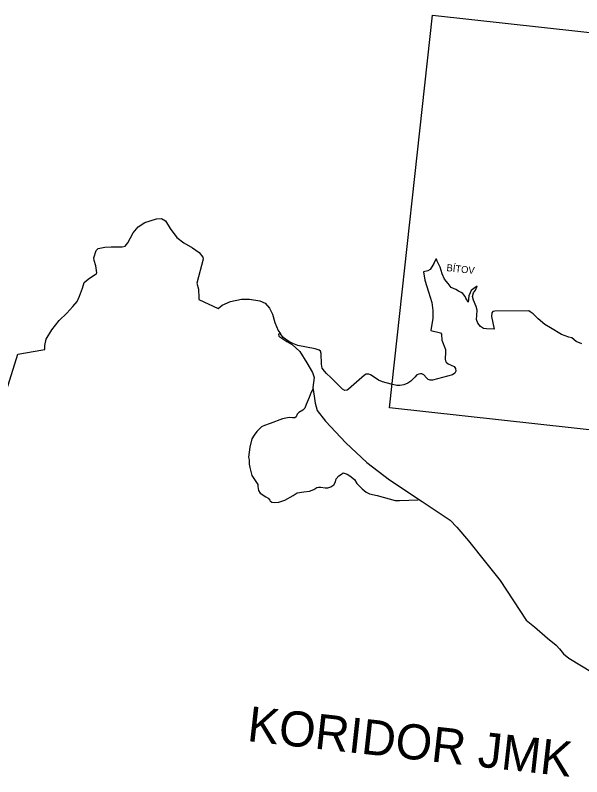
# Model space of a CAD drawing. Extents: x -678204 to -526855, y -1228851 to -1110393.
# Drawn here: x -668785 to -663938, y -1185752 to -1179242 of the extents above; entities that cross this region are included whole.
import ezdxf

# ---------------------------------------------------------------- set-up
doc = ezdxf.new("R2010")
doc.units = 0
for name, color, linetype in [('00_n_cyklo popisy', 7, 'Continuous'), ('00_n_cyklo popisy detaily', 7, 'Continuous'), ('00_n_cyklo prujezdne rekreacni hlavni', 7, 'Continuous'), ('00_n_cyklo prujezdne rekreacni vedlejsi', 7, 'Continuous'), ('00_n_cyklo studie rekreacni vedlejsi', 7, 'Continuous'), ('00_n_cyklo trasovani rekreacni hlavni', 7, 'Continuous'), ('00_n_cyklo trasovani rekreacni vedlejsi', 7, 'Continuous'), ('_HELP', 7, 'Continuous'), ('n_osa_okruh 0 ZAKLADNI', 7, 'Continuous')]:
    doc.layers.add(name, color=color, linetype=linetype)

msp = doc.modelspace()

# ---------------------------------------------------------------- linework, layer by layer
at = {"layer": '00_n_cyklo prujezdne rekreacni hlavni'}
msp.add_lwpolyline([(-668873.8, -1182495.3), (-668764.3, -1182138.1), (-668550.3, -1182100.6), (-668532.5, -1182098.6), (-668532.5, -1182066.1), (-668521.7, -1182011.8), (-668471.4, -1181931.9), (-668409.2, -1181851), (-668343.2, -1181787.9), (-668291.9, -1181732.6), (-668255.4, -1181688.2), (-668235.7, -1181641.9), (-668210, -1181573.8), (-668196.2, -1181527.4), (-668160.7, -1181497.8), (-668089.7, -1181449.5), (-668085.8, -1181444.5), (-668096.6, -1181384.3), (-668110.4, -1181337), (-668111.4, -1181314.3), (-668092.7, -1181253.1), (-668076.9, -1181235.4), (-668019.7, -1181223.5), (-667963.5, -1181221.6), (-667914.1, -1181221.6), (-667870.7, -1181221.6), (-667844.1, -1181215.6), (-667821.4, -1181188), (-667777.1, -1181102.2), (-667734.6, -1181050.9), (-667676.5, -1181012.4), (-667577.8, -1180981.8), (-667534.4, -1180979.8), (-667500.9, -1180998.6), (-667459.5, -1181064.7), (-667403.3, -1181141.6), (-667343.1, -1181188), (-667269.1, -1181230.4), (-667211.9, -1181269.9), (-667181.4, -1181309.4), (-667176.4, -1181327.1), (-667230.2, -1181533.3), (-667218.1, -1181583.4), (-667214.6, -1181657.6), (-667212.9, -1181671.4), (-667049, -1181749.1), (-667015.7, -1181718.8), (-666943.7, -1181688.2), (-666848, -1181668.5), (-666779.9, -1181667.5), (-666693.2, -1181682.3), (-666647.8, -1181703), (-666610.3, -1181746.4), (-666583.7, -1181796.7), (-666563, -1181867.8), (-666535.4, -1181937.8), (-666516.6, -1181966.4), (-666531.4, -1181969.4), (-666530.4, -1181986.2), (-666462.4, -1182029.6), (-666417, -1182056.2), (-666349.9, -1182115.4), (-666289.8, -1182214.1), (-666241.5, -1182296.9), (-666227.6, -1182338.4), (-666239.5, -1182423.2), (-666227.6, -1182498.2), (-666219.7, -1182558), (-666200.7, -1182621.9), (-666131.7, -1182711.7), (-665955.6, -1182896.4), (-665777.8, -1183063.9), (-665582.8, -1183214.1), (-665304.9, -1183397.1), (-665063.3, -1183557.4), (-665006.1, -1183616.6), (-664908.5, -1183735), (-664751.6, -1183930.4), (-664637.2, -1184072.4), (-664413.4, -1184412.8), (-664343.3, -1184470), (-664229.9, -1184567.4), (-664156.7, -1184627.2), (-664127.3, -1184659.3), (-664095.2, -1184699.9), (-664050.1, -1184736.6), (-663846.7, -1184860)], dxfattribs=at)
at = {"layer": '00_n_cyklo prujezdne rekreacni vedlejsi'}
for points in [[(-665204.3, -1181363.3), (-665212.4, -1181379.4), (-665235.4, -1181416.1), (-665253.7, -1181426), (-665291.5, -1181434.6), (-665279.4, -1181506.5), (-665249.7, -1181607.5), (-665221.4, -1181697.5), (-665212, -1181765.9), (-665213.1, -1181831.2), (-665229.1, -1181935.8), (-665146.9, -1181957.9), (-665138.4, -1181967.8), (-665134.3, -1182020.6), (-665103.4, -1182098.3), (-665102.5, -1182121.6), (-665106.5, -1182182.9), (-665103, -1182196.3), (-665096.8, -1182208.3), (-665082.2, -1182220.3), (-665029.6, -1182244), (-665018.3, -1182261.9), (-665016.1, -1182283.3), (-665025.3, -1182301.5), (-665044.4, -1182314.9), (-665215.6, -1182362.3), (-665234.1, -1182361.8), (-665251.3, -1182355.3), (-665266.6, -1182340.4), (-665288, -1182314.4), (-665305.2, -1182308), (-665316.8, -1182306.1), (-665330.9, -1182309.3), (-665348.1, -1182316.1), (-665365.4, -1182334.7), (-665401.5, -1182371.2), (-665425.9, -1182387.7), (-665461.3, -1182401.9), (-665493.5, -1182407.3), (-665519.9, -1182406.7), (-665569.7, -1182396), (-665643.6, -1182376.8), (-665677.4, -1182361.4), (-665722.6, -1182331.2), (-665746.4, -1182316.2), (-665760, -1182309.6), (-665769.6, -1182308.8), (-665781.3, -1182310.3), (-665796.2, -1182319.2), (-665935.2, -1182438.8), (-665945.3, -1182445.8), (-665966.2, -1182448.2), (-665985.7, -1182438.6), (-666056.4, -1182368.1), (-666085.8, -1182338.5), (-666122.9, -1182305), (-666140.3, -1182283.8), (-666159.2, -1182259.5), (-666165.9, -1182224.7), (-666168.4, -1182133.9), (-666172.4, -1182112.2), (-666184, -1182105.1), (-666220, -1182094.2), (-666367.1, -1182064), (-666408.9, -1182049.2), (-666443.6, -1182031.2), (-666493.1, -1181996.5), (-666516.6, -1181966.4)], [(-663937, -1182049.9), (-663985.4, -1182031.9), (-664023.6, -1181999.3), (-664049.5, -1181992.6), (-664112.5, -1181970.1), (-664205.8, -1181912.7), (-664255.3, -1181885.7), (-664309.8, -1181836.8), (-664352.5, -1181794), (-664379.5, -1181777.2), (-664389.7, -1181769.3), (-664683.2, -1181771.5), (-664698.9, -1181773.8), (-664706.8, -1181786.2), (-664710.1, -1181817.7), (-664688.8, -1181924.5), (-664752.9, -1181922.3), (-664777.6, -1181920), (-664804.6, -1181903.1), (-664827.1, -1181875), (-664839.5, -1181842.4), (-664837.2, -1181807.5), (-664832.7, -1181762.6), (-664840.6, -1181731.1), (-664865.3, -1181678.2), (-664874.3, -1181646.7), (-664865.3, -1181615.2), (-664846.2, -1181590.5), (-664833.8, -1181557.8), (-664861.1, -1181576.7), (-664884.5, -1181596), (-664893.9, -1181615.7), (-664904.7, -1181639.7), (-664910.3, -1181695.2)], [(-666236, -1182436.1), (-666254, -1182462.6), (-666271.7, -1182510), (-666297.2, -1182570.4), (-666308.2, -1182600.6), (-666324.2, -1182617.3), (-666359.6, -1182638.5), (-666372.4, -1182652), (-666381.4, -1182673.8), (-666394.3, -1182684.1), (-666413.5, -1182683.5), (-666438.6, -1182680.9), (-666455.9, -1182684.1), (-666497.1, -1182693.1), (-666603.7, -1182732.3), (-666651.9, -1182749), (-666677, -1182760.6), (-666717.5, -1182800.5), (-666741.3, -1182830.7), (-666759.9, -1182864.1), (-666779.2, -1182933.5), (-666790.7, -1183019), (-666782.7, -1183041.3), (-666783.3, -1183078.3), (-666778.8, -1183108.4), (-666760.9, -1183176.4), (-666709.5, -1183253.7), (-666708.9, -1183270.5), (-666702.4, -1183305.8), (-666688.3, -1183326.4), (-666640.8, -1183357.2), (-666620.2, -1183368.8), (-666607.3, -1183386.8), (-666603.5, -1183393.2), (-666590.6, -1183403.5), (-666566.2, -1183408), (-666528.9, -1183404.1), (-666479.5, -1183386.1), (-666406.9, -1183346.3), (-666372.2, -1183325.7), (-666316.3, -1183315.4), (-666267.4, -1183309), (-666231.4, -1183296.8), (-666205.1, -1183279.5), (-666190.9, -1183276.2), (-666170.4, -1183276.9), (-666134.4, -1183282.7), (-666110, -1183280.7), (-666084.9, -1183273.7), (-666058.6, -1183255), (-666045.1, -1183229.3), (-666038.7, -1183204.9), (-666017.5, -1183179.2), (-665993.7, -1183163.8), (-665978.9, -1183154.1), (-665945.3, -1183164.7), (-665922.2, -1183179.5), (-665882.3, -1183211.6), (-665862.4, -1183245.1), (-665818.1, -1183288.8), (-665781.5, -1183317.7), (-665754.2, -1183332.8), (-665688, -1183348.2), (-665534.9, -1183389.4), (-665496.3, -1183389.4), (-665338.2, -1183384.9)]]:
    msp.add_lwpolyline(points, dxfattribs=at)
at = {"layer": '00_n_cyklo studie rekreacni vedlejsi'}
for points in [[(-664910.3, -1181695.2), (-664920.9, -1181675.9), (-664928.6, -1181660.2), (-664936, -1181645.9), (-664947, -1181631), (-664955.1, -1181621.5), (-664971.2, -1181610.8), (-664992.6, -1181599.4), (-665016.4, -1181585.2), (-665055.7, -1181569.1), (-665081.9, -1181536.3), (-665112.2, -1181496.8), (-665131.3, -1181453), (-665150.3, -1181396.2), (-665175.5, -1181345.3), (-665181.6, -1181327), (-665186.1, -1181327.3), (-665204.3, -1181363.3)], [(-664910.3, -1181695.2), (-664910.3, -1181695.2)]]:
    msp.add_lwpolyline(points, dxfattribs=at)
at = {"layer": '00_n_cyklo trasovani rekreacni hlavni'}
msp.add_lwpolyline([(-668873.8, -1182495.3), (-668764.3, -1182138.1), (-668550.3, -1182100.6), (-668532.5, -1182098.6), (-668532.5, -1182066.1), (-668521.7, -1182011.8), (-668471.4, -1181931.9), (-668409.2, -1181851), (-668343.2, -1181787.9), (-668291.9, -1181732.6), (-668255.4, -1181688.2), (-668235.7, -1181641.9), (-668210, -1181573.8), (-668196.2, -1181527.4), (-668160.7, -1181497.8), (-668089.7, -1181449.5), (-668085.8, -1181444.5), (-668096.6, -1181384.3), (-668110.4, -1181337), (-668111.4, -1181314.3), (-668092.7, -1181253.1), (-668076.9, -1181235.4), (-668019.7, -1181223.5), (-667963.5, -1181221.6), (-667914.1, -1181221.6), (-667870.7, -1181221.6), (-667844.1, -1181215.6), (-667821.4, -1181188), (-667777.1, -1181102.2), (-667734.6, -1181050.9), (-667676.5, -1181012.4), (-667577.8, -1180981.8), (-667534.4, -1180979.8), (-667500.9, -1180998.6), (-667459.5, -1181064.7), (-667403.3, -1181141.6), (-667343.1, -1181188), (-667269.1, -1181230.4), (-667211.9, -1181269.9), (-667181.4, -1181309.4), (-667176.4, -1181327.1), (-667230.2, -1181533.3), (-667218.1, -1181583.4), (-667214.6, -1181657.6), (-667212.9, -1181671.4), (-667049, -1181749.1), (-667015.7, -1181718.8), (-666943.7, -1181688.2), (-666848, -1181668.5), (-666779.9, -1181667.5), (-666693.2, -1181682.3), (-666647.8, -1181703), (-666610.3, -1181746.4), (-666583.7, -1181796.7), (-666563, -1181867.8), (-666535.4, -1181937.8), (-666516.6, -1181966.4), (-666531.4, -1181969.4), (-666530.4, -1181986.2), (-666462.4, -1182029.6), (-666417, -1182056.2), (-666349.9, -1182115.4), (-666289.8, -1182214.1), (-666241.5, -1182296.9), (-666227.6, -1182338.4), (-666239.5, -1182423.2), (-666227.6, -1182498.2), (-666219.7, -1182558), (-666200.7, -1182621.9), (-666131.7, -1182711.7), (-665955.6, -1182896.4), (-665777.8, -1183063.9), (-665582.8, -1183214.1), (-665304.9, -1183397.1), (-665063.3, -1183557.4), (-665006.1, -1183616.6), (-664908.5, -1183735), (-664751.6, -1183930.4), (-664637.2, -1184072.4), (-664413.4, -1184412.8), (-664343.3, -1184470), (-664229.9, -1184567.4), (-664156.7, -1184627.2), (-664127.3, -1184659.3), (-664095.2, -1184699.9), (-664050.1, -1184736.6), (-663846.7, -1184860)], dxfattribs=at)
at = {"layer": '00_n_cyklo trasovani rekreacni vedlejsi'}
for points in [[(-664910.3, -1181695.2), (-664920.9, -1181675.9), (-664928.6, -1181660.2), (-664936, -1181645.9), (-664947, -1181631), (-664955.1, -1181621.5), (-664971.2, -1181610.8), (-664992.6, -1181599.4), (-665016.4, -1181585.2), (-665055.7, -1181569.1), (-665081.9, -1181536.3), (-665112.2, -1181496.8), (-665131.3, -1181453), (-665150.3, -1181396.2), (-665175.5, -1181345.3), (-665181.6, -1181327), (-665186.1, -1181327.3), (-665212.4, -1181379.4), (-665235.4, -1181416.1), (-665253.7, -1181426), (-665291.5, -1181434.6), (-665279.4, -1181506.5), (-665249.7, -1181607.5), (-665221.4, -1181697.5), (-665212, -1181765.9), (-665213.1, -1181831.2), (-665229.1, -1181935.8), (-665146.9, -1181957.9), (-665138.4, -1181967.8), (-665134.3, -1182020.6), (-665103.4, -1182098.3), (-665102.5, -1182121.6), (-665106.5, -1182182.9), (-665103, -1182196.3), (-665096.8, -1182208.3), (-665082.2, -1182220.3), (-665029.6, -1182244), (-665018.3, -1182261.9), (-665016.1, -1182283.3), (-665025.3, -1182301.5), (-665044.4, -1182314.9), (-665215.6, -1182362.3), (-665234.1, -1182361.8), (-665251.3, -1182355.3), (-665266.6, -1182340.4), (-665288, -1182314.4), (-665305.2, -1182308), (-665316.8, -1182306.1), (-665330.9, -1182309.3), (-665348.1, -1182316.1), (-665365.4, -1182334.7), (-665401.5, -1182371.2), (-665425.9, -1182387.7), (-665461.3, -1182401.9), (-665493.5, -1182407.3), (-665519.9, -1182406.7), (-665569.7, -1182396), (-665643.6, -1182376.8), (-665677.4, -1182361.4), (-665722.6, -1182331.2), (-665746.4, -1182316.2), (-665760, -1182309.6), (-665769.6, -1182308.8), (-665781.3, -1182310.3), (-665796.2, -1182319.2), (-665935.2, -1182438.8), (-665945.3, -1182445.8), (-665966.2, -1182448.2), (-665985.7, -1182438.6), (-666056.4, -1182368.1), (-666085.8, -1182338.5), (-666122.9, -1182305), (-666140.3, -1182283.8), (-666159.2, -1182259.5), (-666165.9, -1182224.7), (-666168.4, -1182133.9), (-666172.4, -1182112.2), (-666184, -1182105.1), (-666220, -1182094.2), (-666367.1, -1182064), (-666408.9, -1182049.2), (-666443.6, -1182031.2), (-666493.1, -1181996.5), (-666516.6, -1181966.4)], [(-663937, -1182049.9), (-663985.4, -1182031.9), (-664023.6, -1181999.3), (-664049.5, -1181992.6), (-664112.5, -1181970.1), (-664205.8, -1181912.7), (-664255.3, -1181885.7), (-664309.8, -1181836.8), (-664352.5, -1181794), (-664379.5, -1181777.2), (-664389.7, -1181769.3), (-664683.2, -1181771.5), (-664698.9, -1181773.8), (-664706.8, -1181786.2), (-664710.1, -1181817.7), (-664688.8, -1181924.5), (-664752.9, -1181922.3), (-664777.6, -1181920), (-664804.6, -1181903.1), (-664827.1, -1181875), (-664839.5, -1181842.4), (-664837.2, -1181807.5), (-664832.7, -1181762.6), (-664840.6, -1181731.1), (-664865.3, -1181678.2), (-664874.3, -1181646.7), (-664865.3, -1181615.2), (-664846.2, -1181590.5), (-664833.8, -1181557.8), (-664861.1, -1181576.7), (-664884.5, -1181596), (-664893.9, -1181615.7), (-664904.7, -1181639.7), (-664910.3, -1181695.2)], [(-666236, -1182436.1), (-666254, -1182462.6), (-666271.7, -1182510), (-666297.2, -1182570.4), (-666308.2, -1182600.6), (-666324.2, -1182617.3), (-666359.6, -1182638.5), (-666372.4, -1182652), (-666381.4, -1182673.8), (-666394.3, -1182684.1), (-666413.5, -1182683.5), (-666438.6, -1182680.9), (-666455.9, -1182684.1), (-666497.1, -1182693.1), (-666603.7, -1182732.3), (-666651.9, -1182749), (-666677, -1182760.6), (-666717.5, -1182800.5), (-666741.3, -1182830.7), (-666759.9, -1182864.1), (-666779.2, -1182933.5), (-666790.7, -1183019), (-666782.7, -1183041.3), (-666783.3, -1183078.3), (-666778.8, -1183108.4), (-666760.9, -1183176.4), (-666709.5, -1183253.7), (-666708.9, -1183270.5), (-666702.4, -1183305.8), (-666688.3, -1183326.4), (-666640.8, -1183357.2), (-666620.2, -1183368.8), (-666607.3, -1183386.8), (-666603.5, -1183393.2), (-666590.6, -1183403.5), (-666566.2, -1183408), (-666528.9, -1183404.1), (-666479.5, -1183386.1), (-666406.9, -1183346.3), (-666372.2, -1183325.7), (-666316.3, -1183315.4), (-666267.4, -1183309), (-666231.4, -1183296.8), (-666205.1, -1183279.5), (-666190.9, -1183276.2), (-666170.4, -1183276.9), (-666134.4, -1183282.7), (-666110, -1183280.7), (-666084.9, -1183273.7), (-666058.6, -1183255), (-666045.1, -1183229.3), (-666038.7, -1183204.9), (-666017.5, -1183179.2), (-665993.7, -1183163.8), (-665978.9, -1183154.1), (-665945.3, -1183164.7), (-665922.2, -1183179.5), (-665882.3, -1183211.6), (-665862.4, -1183245.1), (-665818.1, -1183288.8), (-665781.5, -1183317.7), (-665754.2, -1183332.8), (-665688, -1183348.2), (-665534.9, -1183389.4), (-665496.3, -1183389.4), (-665338.2, -1183384.9)]]:
    msp.add_lwpolyline(points, dxfattribs=at)
at = {"layer": '_HELP'}
msp.add_lwpolyline([(-665214.8, -1179241.7), (-660500.2, -1179759.4), (-660868.9, -1183116.9), (-665583.5, -1182599.2)], close=True, dxfattribs=at)
at = {"layer": 'n_osa_okruh 0 ZAKLADNI'}
for points in [[(-664910.3, -1181695.2), (-664920.9, -1181675.9), (-664928.6, -1181660.2), (-664936, -1181645.9), (-664947, -1181631), (-664955.1, -1181621.5), (-664971.2, -1181610.8), (-664992.6, -1181599.4), (-665016.4, -1181585.2), (-665055.7, -1181569.1), (-665081.9, -1181536.3), (-665112.2, -1181496.8), (-665131.3, -1181453), (-665150.3, -1181396.2), (-665175.5, -1181345.3), (-665181.6, -1181327), (-665186.1, -1181327.3), (-665212.4, -1181379.4), (-665235.4, -1181416.1), (-665253.7, -1181426), (-665291.5, -1181434.6)], [(-664910.3, -1181695.2), (-664910.3, -1181695.2)], [(-666236, -1182436.1), (-666254, -1182462.6), (-666271.7, -1182510), (-666297.2, -1182570.4), (-666308.2, -1182600.6), (-666324.2, -1182617.3), (-666359.6, -1182638.5), (-666372.4, -1182652), (-666381.4, -1182673.8), (-666394.3, -1182684.1), (-666413.5, -1182683.5), (-666438.6, -1182680.9), (-666455.9, -1182684.1), (-666497.1, -1182693.1), (-666603.7, -1182732.3), (-666651.9, -1182749), (-666677, -1182760.6), (-666717.5, -1182800.5), (-666741.3, -1182830.7), (-666759.9, -1182864.1), (-666779.2, -1182933.5), (-666790.7, -1183019), (-666782.7, -1183041.3), (-666783.3, -1183078.3), (-666778.8, -1183108.4), (-666760.9, -1183176.4), (-666709.5, -1183253.7), (-666708.9, -1183270.5), (-666702.4, -1183305.8), (-666688.3, -1183326.4), (-666640.8, -1183357.2), (-666620.2, -1183368.8), (-666607.3, -1183386.8), (-666603.5, -1183393.2), (-666590.6, -1183403.5), (-666566.2, -1183408), (-666528.9, -1183404.1), (-666479.5, -1183386.1), (-666406.9, -1183346.3), (-666372.2, -1183325.7), (-666316.3, -1183315.4), (-666267.4, -1183309), (-666231.4, -1183296.8), (-666205.1, -1183279.5), (-666190.9, -1183276.2), (-666170.4, -1183276.9), (-666134.4, -1183282.7), (-666110, -1183280.7), (-666084.9, -1183273.7), (-666058.6, -1183255), (-666045.1, -1183229.3), (-666038.7, -1183204.9), (-666017.5, -1183179.2), (-665993.7, -1183163.8), (-665978.9, -1183154.1), (-665945.3, -1183164.7), (-665922.2, -1183179.5), (-665882.3, -1183211.6), (-665862.4, -1183245.1), (-665818.1, -1183288.8), (-665781.5, -1183317.7), (-665754.2, -1183332.8), (-665688, -1183348.2), (-665534.9, -1183389.4), (-665496.3, -1183389.4), (-665338.2, -1183384.9)]]:
    msp.add_lwpolyline(points, dxfattribs=at)

# ---------------------------------------------------------------- texts
at = {"layer": '00_n_cyklo popisy'}
msp.add_text('KORIDOR JMK', height=300, rotation=353.68355, dxfattribs=at).set_placement((-666807.5, -1185445.5))
at = {"layer": '00_n_cyklo popisy detaily'}
msp.add_text('BÍTOV', height=60, rotation=353.68355, dxfattribs=at).set_placement((-665097.4, -1181428.1))

doc.saveas('drawing.dxf')
